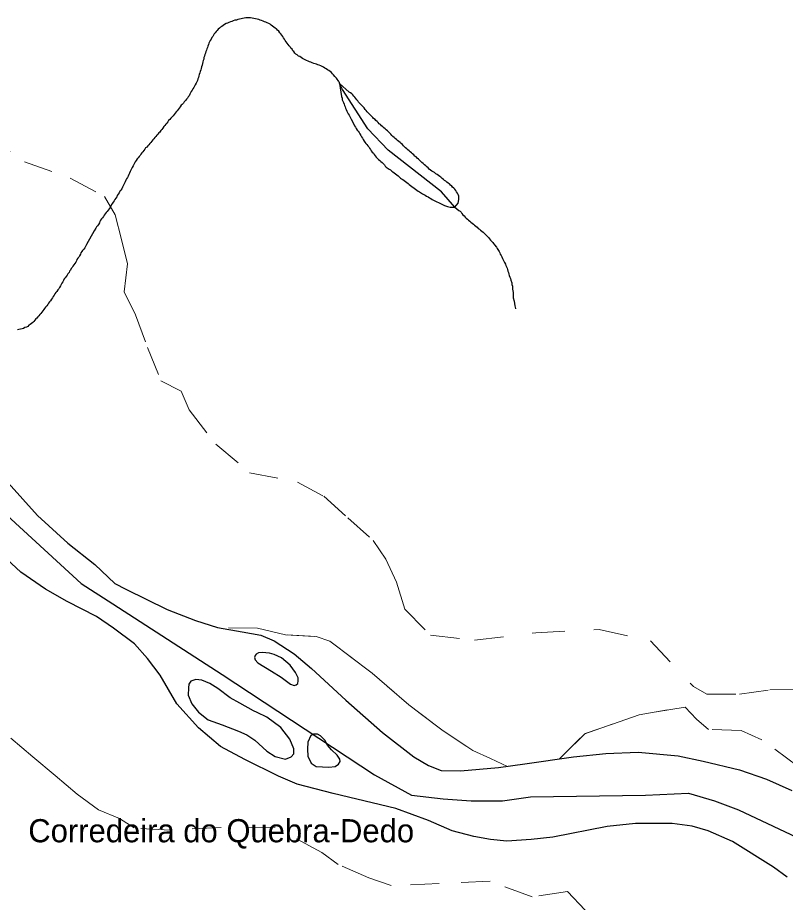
# Model space of a CAD drawing. Extents: x 785.9 to 812.4, y 7674.9 to 7703.1.
# Drawn here: x 790.935 to 793.585, y 7687.529 to 7690.584 of the extents above; entities that cross this region are included whole.
import ezdxf

# ---------------------------------------------------------------- set-up
doc = ezdxf.new("R2010")
doc.units = 0
doc.header["$LTSCALE"] = 0.04
doc.linetypes.add('SHORT_DASHED', pattern=[2.7, 1.5, -1.2])
for name, color, linetype, lineweight in [('2', 7, 'Continuous', 25), ('21', 7, 'SHORT_DASHED', 13), ('55', 7, 'Continuous', 25), ('7', 7, 'Continuous', 25)]:
    doc.layers.add(name, color=color, linetype=linetype, lineweight=lineweight)
doc.layers.add('61', color=7, linetype='Continuous')

msp = doc.modelspace()

# ---------------------------------------------------------------- linework, layer by layer
at = {"layer": '2'}
msp.add_line((792.4449, 7689.9289), (792.4554, 7689.9435), dxfattribs=at)
for points in [[(792.4554, 7689.9435), (792.4579, 7689.9556), (792.4587, 7689.9677), (792.4554, 7689.9726), (792.4538, 7689.9775), (792.4506, 7689.9823), (792.4474, 7689.9872), (792.4441, 7689.9912), (792.4409, 7689.9953), (792.4368, 7689.9985), (792.4336, 7690.0025), (792.4296, 7690.0058), (792.4263, 7690.0098), (792.4215, 7690.0123), (792.4174, 7690.0155), (792.4134, 7690.0187), (792.4093, 7690.022), (792.4053, 7690.0252), (792.4004, 7690.0284), (792.3964, 7690.0325), (792.3923, 7690.0357), (792.3883, 7690.039), (792.3834, 7690.0422), (792.3786, 7690.0446), (792.3745, 7690.0487), (792.3697, 7690.0511), (792.3656, 7690.0543), (792.3608, 7690.0576), (792.3559, 7690.0608), (792.3519, 7690.0648), (792.3478, 7690.0689), (792.3438, 7690.0721), (792.3397, 7690.0762), (792.3357, 7690.0802), (792.3308, 7690.0835), (792.3268, 7690.0875), (792.3227, 7690.0915), (792.3187, 7690.0956), (792.3147, 7690.0988), (792.3114, 7690.1029), (792.3066, 7690.1061), (792.3025, 7690.1102), (792.2985, 7690.1134), (792.2944, 7690.1166), (792.2904, 7690.1207), (792.2863, 7690.1239), (792.2823, 7690.1271), (792.2782, 7690.1312), (792.2742, 7690.1344), (792.2702, 7690.1377), (792.2669, 7690.1417), (792.2637, 7690.1458), (792.2596, 7690.149), (792.2556, 7690.153), (792.2515, 7690.1563), (792.2467, 7690.1595), (792.2434, 7690.1636), (792.2386, 7690.166), (792.2354, 7690.17), (792.2305, 7690.1733), (792.2273, 7690.1773), (792.2232, 7690.1814), (792.22, 7690.1854), (792.2159, 7690.1895), (792.2119, 7690.1927), (792.2078, 7690.1967), (792.2038, 7690.2), (792.1998, 7690.2032), (792.1957, 7690.2073), (792.1917, 7690.2105), (792.1876, 7690.2145), (792.1836, 7690.2178), (792.1803, 7690.2218), (792.1763, 7690.2251), (792.1722, 7690.2283), (792.169, 7690.2323), (792.1642, 7690.2356), (792.1609, 7690.2396), (792.1569, 7690.2437), (792.1536, 7690.2477), (792.1496, 7690.2509), (792.1455, 7690.255), (792.1415, 7690.259), (792.1383, 7690.2631), (792.135, 7690.2671), (792.1318, 7690.272), (792.1277, 7690.276), (792.1237, 7690.2801), (792.1196, 7690.2841), (792.1156, 7690.2882), (792.1124, 7690.2922), (792.1091, 7690.2963), (792.1059, 7690.3003), (792.1027, 7690.3044), (792.0994, 7690.3092), (792.0954, 7690.3133), (792.0921, 7690.3173), (792.0889, 7690.3213), (792.084, 7690.3238), (792.08, 7690.327), (792.046, 7690.3565)], [(792.046, 7690.3565), (792.0533, 7690.3116), (792.0549, 7690.306), (792.0557, 7690.3003), (792.0573, 7690.2955), (792.0598, 7690.2906), (792.0622, 7690.2857), (792.0638, 7690.2809), (792.0654, 7690.276), (792.0671, 7690.2712), (792.0695, 7690.2663), (792.0719, 7690.2615), (792.0743, 7690.2566), (792.076, 7690.2518), (792.0792, 7690.2477), (792.0816, 7690.2429), (792.084, 7690.238), (792.0865, 7690.2331), (792.0921, 7690.2226), (792.0986, 7690.2105), (792.1018, 7690.2056), (792.1043, 7690.2008), (792.1075, 7690.1959), (792.1107, 7690.1919), (792.114, 7690.187), (792.1164, 7690.1822), (792.1196, 7690.1773), (792.1221, 7690.1725), (792.1253, 7690.1676), (792.1277, 7690.1628), (792.131, 7690.1579), (792.1342, 7690.1539), (792.1375, 7690.1498), (792.1407, 7690.1458), (792.1439, 7690.1417), (792.1472, 7690.1377), (792.1496, 7690.1328), (792.1536, 7690.1288), (792.1561, 7690.1239), (792.1593, 7690.1199), (792.1633, 7690.1158), (792.1658, 7690.111), (792.1698, 7690.1069), (792.1731, 7690.1021), (792.1811, 7690.094), (792.1852, 7690.0907), (792.1892, 7690.0875), (792.1933, 7690.0835), (792.1973, 7690.0802), (792.2014, 7690.0762), (792.2038, 7690.0713), (792.2078, 7690.0673), (792.2176, 7690.0608), (792.2224, 7690.0584), (792.2265, 7690.0543), (792.2305, 7690.0511), (792.2345, 7690.0479), (792.2394, 7690.0446), (792.2443, 7690.0414), (792.2483, 7690.0381), (792.2564, 7690.0301), (792.2604, 7690.0268), (792.2653, 7690.0244), (792.2693, 7690.0212), (792.2742, 7690.0179), (792.2782, 7690.0147), (792.2831, 7690.0114), (792.2871, 7690.0082), (792.2912, 7690.0042), (792.296, 7690.0009), (792.3041, 7689.9945), (792.309, 7689.9912), (792.3138, 7689.988), (792.3179, 7689.9847), (792.3227, 7689.9823), (792.3325, 7689.9758), (792.3373, 7689.9734), (792.3422, 7689.971), (792.347, 7689.9677), (792.3519, 7689.9653), (792.3567, 7689.9621), (792.3616, 7689.9588), (792.3664, 7689.9564), (792.3705, 7689.9532), (792.3753, 7689.9508), (792.3802, 7689.9491), (792.3899, 7689.9443), (792.3948, 7689.9419), (792.3996, 7689.9402), (792.4093, 7689.9354), (792.419, 7689.9321), (792.4239, 7689.9305), (792.4287, 7689.9289), (792.4449, 7689.9289)], [(790.9018, 7688.9776), (791.003, 7688.8645), (791.1086, 7688.7686), (791.2012, 7688.6953), (791.2702, 7688.6296), (791.309, 7688.6102), (791.4512, 7688.5401), (791.5492, 7688.5024), (791.6246, 7688.4776), (791.7097, 7688.4625), (791.7743, 7688.4507), (791.8207, 7688.4313), (791.8896, 7688.3871), (791.9499, 7688.3364), (792.0684, 7688.2265), (792.1945, 7688.1155), (792.3033, 7688.0315), (792.3539, 7688.0013), (792.397, 7687.9841), (792.4638, 7687.983), (792.5952, 7687.9937), (792.6857, 7688.0067), (792.8538, 7688.0315), (792.9658, 7688.0423), (793.0779, 7688.0476), (793.2158, 7688.0347), (793.302, 7688.0164), (793.4269, 7687.9862), (793.5206, 7687.9539), (793.6079, 7687.9151)], [(791.7199, 7688.0213), (791.6354, 7688.0672), (791.5589, 7688.1308), (791.4846, 7688.2137), (791.4275, 7688.3129), (791.3833, 7688.3711), (791.3381, 7688.4217), (791.2659, 7688.4756), (791.2077, 7688.5154), (791.1065, 7688.5672), (791.031, 7688.6103), (790.9459, 7688.6685), (790.8824, 7688.7278)], [(793.5923, 7687.6151), (793.5449, 7687.6496), (793.4027, 7687.739), (793.3197, 7687.7756), (793.2637, 7687.7918), (793.1947, 7687.8004), (793.0687, 7687.8004), (792.9707, 7687.7907), (792.7832, 7687.7541), (792.7078, 7687.7455), (792.6238, 7687.7401), (792.5678, 7687.7455), (792.5096, 7687.7563), (792.4353, 7687.7757), (792.3534, 7687.8112), (792.2403, 7687.8532), (792.0248, 7687.9049), (791.8998, 7687.9362), (791.8352, 7687.9642), (791.7199, 7688.0213)]]:
    msp.add_lwpolyline(points, dxfattribs=at)
for points in [[(791.804, 7688.3887), (791.7797, 7688.3916), (791.767, 7688.3905), (791.7587, 7688.3858), (791.7547, 7688.3807), (791.7532, 7688.3742), (791.7554, 7688.3662), (791.7641, 7688.3553), (791.8116, 7688.3273), (791.845, 7688.3067), (791.8773, 7688.2824), (791.8893, 7688.2776), (791.8969, 7688.2795), (791.9027, 7688.2849), (791.9041, 7688.2932), (791.9038, 7688.3041), (791.8943, 7688.3223), (791.8762, 7688.3473), (791.8465, 7688.3727), (791.8211, 7688.3843)], [(791.7496, 7688.19), (791.7022, 7688.2159), (791.6688, 7688.2353), (791.6257, 7688.2676), (791.5988, 7688.2838), (791.5708, 7688.2956), (791.5503, 7688.2978), (791.5331, 7688.2924), (791.5255, 7688.2816), (791.5245, 7688.2698), (791.5234, 7688.2439), (791.5363, 7688.2137), (791.56, 7688.1857), (791.5923, 7688.1588), (791.6408, 7688.1415), (791.6979, 7688.12), (791.7259, 7688.1071), (791.7539, 7688.0887), (791.7949, 7688.051), (791.8239, 7688.0327), (791.8595, 7688.023), (791.8789, 7688.0306), (791.8886, 7688.0413), (791.8886, 7688.0586), (791.8746, 7688.092), (791.8433, 7688.1329), (791.7949, 7688.1685), (791.7625, 7688.1846)], [(791.9472, 7688.1053), (791.9365, 7688.0816), (791.9354, 7688.0579), (791.9365, 7688.0332), (791.9483, 7688.0094), (791.9655, 7687.9976), (792.0097, 7687.9954), (792.0313, 7687.9976), (792.0431, 7688.0062), (792.0485, 7688.0148), (792.0474, 7688.0235), (792.0377, 7688.0364), (792.0183, 7688.0547), (792.0043, 7688.0719), (791.9957, 7688.0892), (791.9806, 7688.1032), (791.9699, 7688.1097), (791.9569, 7688.1097)]]:
    msp.add_lwpolyline(points, close=True, dxfattribs=at)
at = {"layer": '21'}
msp.add_line((793.2787, 7688.1609), (793.2393, 7688.203), dxfattribs=at)
for points in [[(790.8259, 7690.1762), (790.9589, 7690.0862), (791.1166, 7690.0295), (791.2344, 7689.9657), (791.2717, 7689.9032), (791.2931, 7689.8183), (791.3145, 7689.7334), (791.3033, 7689.6369), (791.3414, 7689.5578), (791.3831, 7689.4446), (791.4299, 7689.33), (791.4999, 7689.2944), (791.5267, 7689.2291), (791.6198, 7689.1108), (791.7354, 7689.0121), (791.901, 7688.9801), (791.9927, 7688.9308), (792.075, 7688.8561), (792.1623, 7688.7785), (792.2062, 7688.714), (792.2435, 7688.6341), (792.2714, 7688.5405), (792.3609, 7688.4513), (792.5128, 7688.4338), (792.7241, 7688.4592), (792.9427, 7688.4709), (793.1199, 7688.4317), (793.2681, 7688.2742), (793.315, 7688.2478), (793.4277, 7688.2477)], [(792.6261, 7687.9981), (792.5679, 7688.0255), (792.5069, 7688.0525), (792.4001, 7688.1242), (792.2862, 7688.2103), (792.1589, 7688.3198), (792.0127, 7688.431), (791.9652, 7688.4463), (791.8593, 7688.4525), (791.7634, 7688.475), (791.6246, 7688.4776)], [(791.7634, 7688.475), (791.8593, 7688.4525), (791.9652, 7688.4463), (792.0127, 7688.431), (792.1589, 7688.3198), (792.2862, 7688.2103), (792.4001, 7688.1242), (792.5069, 7688.0525), (792.5679, 7688.0255), (792.6261, 7687.9981)], [(793.4277, 7688.2477), (793.5322, 7688.2623), (793.6376, 7688.2636), (793.8099, 7688.1288), (793.8767, 7688.092), (794.0001, 7688.0872), (794.1332, 7687.9973), (794.2028, 7688.0143), (794.2397, 7687.9901), (794.2528, 7687.9303), (794.2298, 7687.897), (794.1599, 7687.8626), (794.105, 7687.8316), (794.012, 7687.8276), (793.9595, 7687.8479), (793.8273, 7687.8555), (793.6298, 7687.9981), (793.5044, 7688.0897), (793.4326, 7688.1217), (793.3204, 7688.1253), (793.2787, 7688.1609)], [(792.8061, 7688.0245), (792.893, 7688.1109), (792.989, 7688.1442), (793.0807, 7688.1762), (793.238, 7688.2042)], [(793.2393, 7688.203), (793.0807, 7688.1762), (792.989, 7688.1442), (792.893, 7688.1109), (792.8061, 7688.0245)], [(792.8941, 7687.5014), (792.834, 7687.5659), (792.7111, 7687.548), (792.5666, 7687.6011), (792.3909, 7687.5938), (792.2252, 7687.5865), (792.1472, 7687.6132), (792.0415, 7687.659), (791.9854, 7687.7003), (791.8244, 7687.7882), (791.6379, 7687.7869), (791.4604, 7687.7779), (791.3369, 7687.7856), (791.2863, 7687.8178), (791.2142, 7687.8478), (791.1401, 7687.9016), (791.064, 7687.9661), (790.9879, 7688.0306), (790.9118, 7688.0951)]]:
    msp.add_lwpolyline(points, dxfattribs=at)
at = {"layer": '55'}
for points in [[(792.4449, 7689.9289), (792.3981, 7689.9823), (792.2144, 7690.1263), (792.1445, 7690.2004), (792.0567, 7690.3359), (792.046, 7690.3565)], [(790.4039, 7689.1692), (790.4488, 7689.1499), (790.5963, 7689.1178), (790.6989, 7689.0473), (791.1541, 7688.6302), (791.2631, 7688.5596), (791.6414, 7688.3158), (792.1672, 7687.9694), (792.2954, 7687.8988), (792.4044, 7687.886), (792.5006, 7687.8796), (792.6096, 7687.8796), (792.7058, 7687.8924), (793.1033, 7687.8988), (793.2508, 7687.9052), (793.3406, 7687.8796), (793.4239, 7687.8475)], [(793.4239, 7687.8475), (793.6628, 7687.7355), (793.7333, 7687.6842), (793.8167, 7687.6585)]]:
    msp.add_lwpolyline(points, dxfattribs=at)
at = {"layer": '7'}
msp.add_line((792.0437, 7690.3632), (792.046, 7690.3565), dxfattribs=at)
for points in [[(791.8284, 7690.5449), (791.8244, 7690.5482), (791.8195, 7690.5514), (791.8147, 7690.5547), (791.8106, 7690.5579), (791.8066, 7690.5611), (791.8017, 7690.5636), (791.7969, 7690.566), (791.792, 7690.5684), (791.7872, 7690.57), (791.7823, 7690.5717), (791.7775, 7690.5741), (791.7726, 7690.5757), (791.7678, 7690.5773), (791.7621, 7690.5789), (791.7564, 7690.5797), (791.7508, 7690.5814), (791.7451, 7690.5822), (791.7394, 7690.5838), (791.7338, 7690.5838), (791.7281, 7690.583), (791.7225, 7690.583), (791.7168, 7690.5822), (791.7111, 7690.5814), (791.7063, 7690.5797), (791.7006, 7690.5789), (791.6949, 7690.5773), (791.6901, 7690.5757), (791.6844, 7690.5749), (791.6796, 7690.5725), (791.6747, 7690.5708), (791.6699, 7690.5692), (791.6642, 7690.5676), (791.6593, 7690.5652), (791.6545, 7690.5636), (791.6496, 7690.5603), (791.6448, 7690.5571), (791.6399, 7690.5539), (791.6359, 7690.5506), (791.6318, 7690.5474), (791.6278, 7690.5441), (791.6237, 7690.5401), (791.6205, 7690.536), (791.6173, 7690.532), (791.614, 7690.528), (791.6108, 7690.5239), (791.6084, 7690.5191), (791.6051, 7690.515), (791.6027, 7690.5102), (791.5995, 7690.5053), (791.5978, 7690.5004), (791.5954, 7690.4956), (791.5938, 7690.4907), (791.5922, 7690.4859), (791.5906, 7690.481), (791.5881, 7690.4762), (791.5865, 7690.4713), (791.5849, 7690.4665), (791.5833, 7690.4616), (791.5817, 7690.4568), (791.58, 7690.4511), (791.5784, 7690.4462), (791.5776, 7690.4406), (791.576, 7690.4357), (791.5744, 7690.4309), (791.5736, 7690.4252), (791.572, 7690.4195), (791.5703, 7690.4139), (791.5687, 7690.4082), (791.5671, 7690.4033), (791.5647, 7690.3985), (791.5639, 7690.3928), (791.5622, 7690.388), (791.5606, 7690.3831), (791.559, 7690.3775), (791.5566, 7690.3726), (791.5558, 7690.3669), (791.5533, 7690.3621), (791.5509, 7690.3572), (791.5485, 7690.3524), (791.5461, 7690.3475), (791.5436, 7690.3427), (791.5404, 7690.3378), (791.5372, 7690.333), (791.5339, 7690.3289), (791.5323, 7690.3241), (791.5299, 7690.3192), (791.5274, 7690.3143), (791.5242, 7690.3103), (791.521, 7690.3063), (791.5177, 7690.3022), (791.5145, 7690.2974), (791.5105, 7690.2933), (791.5072, 7690.2885), (791.5032, 7690.2844), (791.4991, 7690.2812), (791.4959, 7690.2763), (791.4927, 7690.2715), (791.4894, 7690.2666), (791.4862, 7690.2626), (791.4821, 7690.2585)], [(792.0437, 7690.3632), (792.036, 7690.3745), (792.0349, 7690.3758), (792.0339, 7690.377), (792.0328, 7690.3782), (792.0318, 7690.3795), (792.0307, 7690.3807), (792.0259, 7690.3864), (792.0226, 7690.3904), (792.0186, 7690.3944), (792.0137, 7690.3977), (792.0089, 7690.4009), (792.0048, 7690.4042), (792, 7690.4074), (791.9951, 7690.4098), (791.9911, 7690.4131), (791.9862, 7690.4155), (791.9814, 7690.4171), (791.9765, 7690.4195), (791.9717, 7690.4212), (791.9668, 7690.4228), (791.962, 7690.4244), (791.9571, 7690.426), (791.9522, 7690.4276), (791.9474, 7690.4301), (791.9425, 7690.4317), (791.9377, 7690.4333), (791.9328, 7690.4357), (791.928, 7690.4381), (791.9231, 7690.4406), (791.9183, 7690.443), (791.9134, 7690.4462), (791.9094, 7690.4495), (791.9045, 7690.4511), (791.9005, 7690.4551), (791.8956, 7690.4576), (791.8924, 7690.4616), (791.8891, 7690.4665), (791.8851, 7690.4697), (791.8827, 7690.4746), (791.8786, 7690.4786), (791.8754, 7690.4826), (791.8721, 7690.4867), (791.8689, 7690.4907), (791.8657, 7690.4956), (791.8624, 7690.5004), (791.8592, 7690.5053), (791.856, 7690.5093), (791.8527, 7690.5142), (791.8503, 7690.5191), (791.8471, 7690.5239), (791.8438, 7690.528), (791.8398, 7690.532), (791.8365, 7690.5369), (791.8325, 7690.5409), (791.8284, 7690.5449)], [(791.4821, 7690.2585), (791.4789, 7690.2537), (791.4749, 7690.2496), (791.4716, 7690.2448), (791.4676, 7690.2407), (791.4643, 7690.2367), (791.4603, 7690.2326), (791.4562, 7690.2286), (791.453, 7690.2237), (791.4498, 7690.2197), (791.4465, 7690.2156), (791.4433, 7690.2116), (791.4393, 7690.2075), (791.436, 7690.2027), (791.4328, 7690.1978), (791.4295, 7690.1938), (791.4263, 7690.1889), (791.4223, 7690.1857), (791.419, 7690.1816), (791.4158, 7690.1776), (791.4117, 7690.1736), (791.4085, 7690.1695), (791.4053, 7690.1655), (791.402, 7690.1614), (791.3988, 7690.1574), (791.3947, 7690.1533), (791.3915, 7690.1493), (791.3883, 7690.1452), (791.385, 7690.1412), (791.381, 7690.1371), (791.3769, 7690.1339), (791.3737, 7690.1299), (791.3705, 7690.125), (791.3672, 7690.121), (791.364, 7690.1169), (791.3608, 7690.1129), (791.3575, 7690.108), (791.3543, 7690.104), (791.3511, 7690.0999), (791.3478, 7690.0959), (791.3446, 7690.091), (791.3413, 7690.0862), (791.3381, 7690.0813), (791.3357, 7690.0765), (791.3333, 7690.0716), (791.3308, 7690.0667), (791.3284, 7690.0619), (791.326, 7690.057), (791.3235, 7690.0522), (791.3211, 7690.0473), (791.3187, 7690.0425), (791.3171, 7690.0368), (791.3146, 7690.032), (791.3114, 7690.0271), (791.309, 7690.0222), (791.3066, 7690.0174), (791.3041, 7690.0125), (791.3017, 7690.0077), (791.2993, 7690.0028), (791.2968, 7689.998), (791.2944, 7689.9931), (791.2912, 7689.9883), (791.2879, 7689.9842), (791.2855, 7689.9794), (791.2823, 7689.9745), (791.279, 7689.9696), (791.2774, 7689.9648), (791.2742, 7689.9607), (791.2709, 7689.9559), (791.2677, 7689.9518), (791.2653, 7689.947), (791.262, 7689.9429), (791.2596, 7689.9381), (791.2564, 7689.9332), (791.254, 7689.9284), (791.2507, 7689.9235), (791.2475, 7689.9187), (791.2442, 7689.9146), (791.2402, 7689.9106), (791.237, 7689.9065), (791.2337, 7689.9017), (791.2313, 7689.8968), (791.2281, 7689.8928), (791.2248, 7689.8887), (791.2216, 7689.8847), (791.2192, 7689.8798), (791.2175, 7689.875), (791.2143, 7689.8701), (791.2111, 7689.8653), (791.2078, 7689.8612), (791.2046, 7689.8564), (791.1989, 7689.8475), (791.173, 7689.8005), (791.1714, 7689.7981), (791.1698, 7689.7933), (791.1666, 7689.7892), (791.1633, 7689.7844), (791.1593, 7689.7803), (791.1561, 7689.7763), (791.1536, 7689.7714), (791.152, 7689.7666)], [(792.4449, 7689.9289), (792.4588, 7689.9181), (792.4627, 7689.9152), (792.466, 7689.9127), (792.4692, 7689.9071), (792.4724, 7689.903), (792.4765, 7689.899), (792.4797, 7689.8949), (792.4838, 7689.8917), (792.4878, 7689.8876), (792.4919, 7689.8844), (792.4959, 7689.8812), (792.4999, 7689.8771), (792.504, 7689.8739), (792.5088, 7689.8707), (792.5129, 7689.8674), (792.5169, 7689.8634), (792.521, 7689.8601), (792.525, 7689.8561), (792.5291, 7689.8529), (792.5331, 7689.8496), (792.538, 7689.8464), (792.542, 7689.8431), (792.5453, 7689.8391), (792.5493, 7689.8359), (792.5534, 7689.8318), (792.5614, 7689.8237), (792.5647, 7689.8197), (792.5679, 7689.8156), (792.5712, 7689.8116), (792.5752, 7689.8075), (792.5784, 7689.8035), (792.5817, 7689.7994), (792.5881, 7689.7914), (792.5906, 7689.7865), (792.597, 7689.7768), (792.5995, 7689.7719), (792.6011, 7689.7671), (792.6043, 7689.7622), (792.6068, 7689.7574), (792.6092, 7689.7525), (792.614, 7689.7428), (792.6165, 7689.738), (792.6189, 7689.7331), (792.6205, 7689.7282), (792.6229, 7689.7234), (792.6246, 7689.7185), (792.6262, 7689.7137), (792.6278, 7689.7088), (792.6294, 7689.704), (792.631, 7689.6983), (792.6326, 7689.6934), (792.6343, 7689.6878), (792.6367, 7689.6829), (792.6375, 7689.6773), (792.6407, 7689.6676), (792.6415, 7689.6619), (792.6432, 7689.657), (792.644, 7689.6514), (792.644, 7689.6457), (792.6448, 7689.64), (792.6456, 7689.6344), (792.6456, 7689.6231), (792.6464, 7689.6158), (792.6488, 7689.6044), (792.6521, 7689.5891), (792.6541, 7689.5796), (792.6542, 7689.5788)], [(791.152, 7689.7666), (791.1488, 7689.7617), (791.1463, 7689.7568), (791.1431, 7689.7528), (791.1399, 7689.7488), (791.1382, 7689.7439), (791.1358, 7689.739), (791.1326, 7689.735), (791.1293, 7689.7301), (791.1261, 7689.7253), (791.1229, 7689.7212), (791.1196, 7689.7172), (791.1172, 7689.7123), (791.114, 7689.7083), (791.1124, 7689.7034), (791.1083, 7689.6994), (791.1059, 7689.6945), (791.1026, 7689.6897), (791.0994, 7689.6856), (791.0962, 7689.6816), (791.0929, 7689.6767), (791.0905, 7689.6719), (791.0873, 7689.667), (791.0848, 7689.6622), (791.0824, 7689.6573), (791.08, 7689.6525), (791.0768, 7689.6476), (791.0735, 7689.6436), (791.0703, 7689.6387), (791.067, 7689.6347), (791.0638, 7689.6306), (791.0614, 7689.6258), (791.0581, 7689.6209), (791.0549, 7689.6161), (791.0517, 7689.6112), (791.0484, 7689.6063), (791.0452, 7689.6023), (791.042, 7689.5983), (791.0387, 7689.5934), (791.0355, 7689.5885), (791.0314, 7689.5845), (791.0282, 7689.5796), (791.025, 7689.5756), (791.0217, 7689.5715), (791.0185, 7689.5667), (791.0145, 7689.5626), (791.0112, 7689.5586), (791.008, 7689.5546), (791.0047, 7689.5505), (791.0015, 7689.5465), (790.9975, 7689.5432), (790.9942, 7689.5392), (790.991, 7689.5351), (790.9877, 7689.5311), (790.9829, 7689.5279), (790.978, 7689.5246), (790.974, 7689.5214), (790.9699, 7689.5173), (790.9651, 7689.5149), (790.9602, 7689.5133), (790.9554, 7689.5109), (790.9505, 7689.5092), (790.9449, 7689.5084), (790.9392, 7689.5068), (790.9343, 7689.5052)]]:
    msp.add_lwpolyline(points, dxfattribs=at)

# ---------------------------------------------------------------- texts
at = {"layer": '61'}
msp.add_text('Corredeira do Quebra-Dedo', height=0.08, dxfattribs=at).set_placement((790.9718, 7687.7359))

doc.saveas('drawing.dxf')
